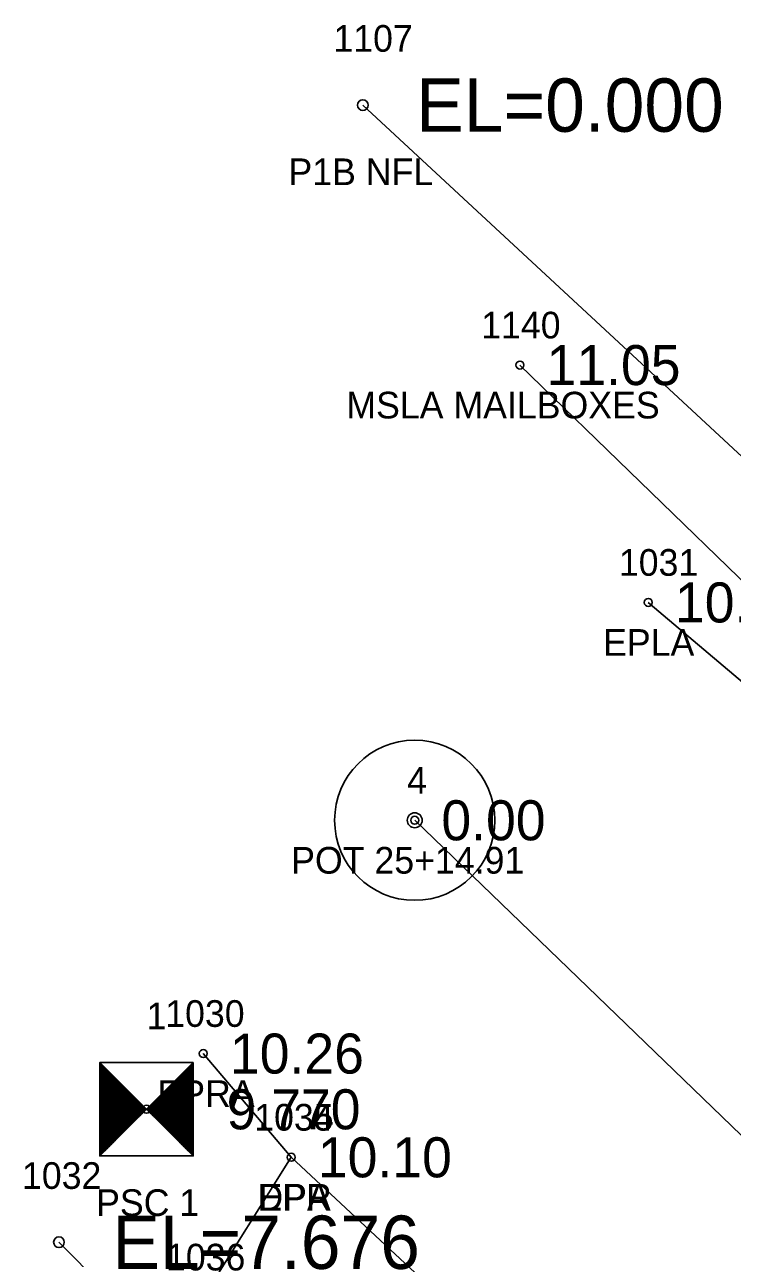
# Model space of a CAD drawing. Extents: x 2608598 to 2610682, y 641451 to 643526.
# Drawn here: x 2608800.2 to 2608826.71, y 643357.31 to 643403.56 of the extents above; entities that cross this region are included whole.
import ezdxf

# ---------------------------------------------------------------- set-up
doc = ezdxf.new("R2010")
doc.units = 0
for name, color, linetype in [('RD_EX_DR_Pipe', 7, 'Continuous'), ('RD_EX_DR_Pipe_txCode', 7, 'Continuous'), ('RD_EX_Driveway', 7, 'Continuous'), ('RD_EX_Driveway_txCode', 7, 'Continuous'), ('RD_EX_Misc', 7, 'Continuous'), ('RD_EX_Misc_txCode', 7, 'Continuous'), ('RD_EX_Road', 7, 'Continuous'), ('RD_EX_Road_txCode', 7, 'Continuous'), ('RD_EX_TX_Driveway_ELEV', 7, 'Continuous'), ('RD_EX_TX_Misc_ELEV', 7, 'Continuous'), ('RD_EX_TX_Road_ELEV', 7, 'Continuous'), ('RD_HC_Cl', 7, 'Continuous'), ('RD_HC_Data', 7, 'Continuous'), ('RD_HC_Survey', 7, 'Continuous'), ('RD_HC_Survey_ELEV', 7, 'Continuous'), ('RD_HC_txCode', 7, 'Continuous'), ('RD_SMD_Locator', 7, 'Continuous'), ('RD_TX_Pipe_ElevEX', 7, 'Continuous')]:
    doc.layers.add(name, color=color, linetype=linetype)

msp = doc.modelspace()

# ---------------------------------------------------------------- linework, layer by layer
at = {"layer": 'RD_EX_DR_Pipe'}
for p, q in [((2608906.801, 643313.376), (2608812.867, 643400.541)), ((2608801.48, 643357.916), (2608816.779, 643342.503))]:
    msp.add_line(p, q, dxfattribs=at)
at = {"layer": 'RD_EX_Driveway'}
msp.add_lwpolyline([(2608810.184, 643361.1), (2608806.9, 643355.858), (2608804.015, 643352.911), (2608810.865, 643346.462), (2608815.199, 643349.433), (2608820.754, 643351.249)], dxfattribs=at)
at = {"layer": 'RD_EX_Misc'}
msp.add_line((2608818.754, 643390.795), (2608829.429, 643380.424), dxfattribs=at)
at = {"layer": 'RD_EX_Road'}
for points in [[(2608823.565, 643381.898), (2608829.584, 643376.805), (2608846.192, 643359.903), (2608852.068, 643354.1), (2608873.124, 643334.611), (2608877.912, 643330.135), (2608897.264, 643311.51), (2608898.769, 643309.298), (2608970.3, 643240.177), (2609042.495, 643170.94), (2609058.512, 643155.458)], [(2608806.889, 643364.989), (2608810.184, 643361.1), (2608820.754, 643351.249), (2608881.81, 643292.235), (2608917.833, 643257.495), (2608933.208, 643242.709), (2608954.068, 643222.833), (2609026.064, 643154.189), (2609039.601, 643139.963), (2609073.879, 643106.954), (2609100.48, 643081.888), (2609124.194, 643058.866), (2609171.612, 643013.711), (2609183.195, 643002.284), (2609197.913, 642988.365), (2609247.586, 642940.954), (2609328.02, 642863.599), (2609402.609, 642790.299), (2609474.235, 642720.69), (2609483.838, 642711.579), (2609495.782, 642699.917), (2609509.808, 642686.45)]]:
    msp.add_lwpolyline(points, dxfattribs=at)
at = {"layer": 'RD_HC_Cl'}
msp.add_line((2608814.812, 643373.733), (2610092.394, 642140.787), dxfattribs=at)
at = {"layer": 'RD_HC_Data'}
for radius in [3, 0.282]:
    msp.add_circle((2608814.812, 643373.733), radius, dxfattribs=at)
at = {"layer": 'RD_HC_Survey'}
for p, q in [((2608803.011, 643364.65), (2608806.511, 643361.15)), ((2608806.511, 643364.65), (2608803.011, 643361.15)), ((2608803.036, 643364.625), (2608803.036, 643361.175)), ((2608803.061, 643364.601), (2608803.061, 643361.2)), ((2608803.086, 643364.576), (2608803.086, 643361.224)), ((2608803.11, 643364.551), (2608803.11, 643361.249)), ((2608803.135, 643364.526), (2608803.135, 643361.274)), ((2608803.16, 643364.502), (2608803.16, 643361.299)), ((2608803.185, 643364.477), (2608803.185, 643361.323)), ((2608803.209, 643364.452), (2608803.209, 643361.348)), ((2608803.234, 643364.427), (2608803.234, 643361.373)), ((2608803.259, 643364.403), (2608803.259, 643361.398)), ((2608803.284, 643364.378), (2608803.284, 643361.422)), ((2608803.308, 643364.353), (2608803.308, 643361.447)), ((2608803.333, 643364.328), (2608803.333, 643361.472)), ((2608803.358, 643364.304), (2608803.358, 643361.497)), ((2608806.165, 643364.304), (2608806.165, 643361.497)), ((2608806.19, 643364.328), (2608806.19, 643361.472)), ((2608806.214, 643364.353), (2608806.214, 643361.447)), ((2608806.239, 643364.378), (2608806.239, 643361.422)), ((2608806.264, 643364.403), (2608806.264, 643361.398)), ((2608806.289, 643364.427), (2608806.289, 643361.373)), ((2608806.313, 643364.452), (2608806.313, 643361.348)), ((2608806.338, 643364.477), (2608806.338, 643361.323)), ((2608806.363, 643364.502), (2608806.363, 643361.299)), ((2608806.388, 643364.526), (2608806.388, 643361.274)), ((2608806.412, 643364.551), (2608806.412, 643361.249)), ((2608806.437, 643364.576), (2608806.437, 643361.224)), ((2608806.462, 643364.601), (2608806.462, 643361.2)), ((2608806.487, 643364.625), (2608806.487, 643361.175)), ((2608803.383, 643364.279), (2608803.383, 643361.521)), ((2608803.407, 643364.254), (2608803.407, 643361.546)), ((2608803.432, 643364.229), (2608803.432, 643361.571)), ((2608803.457, 643364.205), (2608803.457, 643361.596)), ((2608803.482, 643364.18), (2608803.482, 643361.62)), ((2608803.506, 643364.155), (2608803.506, 643361.645)), ((2608803.531, 643364.13), (2608803.531, 643361.67)), ((2608803.556, 643364.106), (2608803.556, 643361.695)), ((2608803.581, 643364.081), (2608803.581, 643361.719)), ((2608803.605, 643364.056), (2608803.605, 643361.744)), ((2608803.63, 643364.031), (2608803.63, 643361.769)), ((2608803.655, 643364.007), (2608803.655, 643361.794)), ((2608803.68, 643363.982), (2608803.68, 643361.818)), ((2608803.704, 643363.957), (2608803.704, 643361.843)), ((2608803.729, 643363.932), (2608803.729, 643361.868)), ((2608803.754, 643363.908), (2608803.754, 643361.893)), ((2608803.779, 643363.883), (2608803.779, 643361.917)), ((2608803.803, 643363.858), (2608803.803, 643361.942)), ((2608805.719, 643363.858), (2608805.719, 643361.942)), ((2608805.744, 643363.883), (2608805.744, 643361.917)), ((2608805.769, 643363.908), (2608805.769, 643361.893)), ((2608805.794, 643363.932), (2608805.794, 643361.868)), ((2608805.818, 643363.957), (2608805.818, 643361.843)), ((2608805.843, 643363.982), (2608805.843, 643361.818)), ((2608805.868, 643364.007), (2608805.868, 643361.794)), ((2608805.893, 643364.031), (2608805.893, 643361.769)), ((2608805.917, 643364.056), (2608805.917, 643361.744)), ((2608805.942, 643364.081), (2608805.942, 643361.719)), ((2608805.967, 643364.106), (2608805.967, 643361.695)), ((2608805.992, 643364.13), (2608805.992, 643361.67)), ((2608806.016, 643364.155), (2608806.016, 643361.645)), ((2608806.041, 643364.18), (2608806.041, 643361.62)), ((2608806.066, 643364.205), (2608806.066, 643361.596)), ((2608806.091, 643364.229), (2608806.091, 643361.571)), ((2608806.115, 643364.254), (2608806.115, 643361.546)), ((2608806.14, 643364.279), (2608806.14, 643361.521)), ((2608803.828, 643363.833), (2608803.828, 643361.967)), ((2608803.853, 643363.809), (2608803.853, 643361.992)), ((2608803.878, 643363.784), (2608803.878, 643362.016)), ((2608803.902, 643363.759), (2608803.902, 643362.041)), ((2608803.927, 643363.734), (2608803.927, 643362.066)), ((2608803.952, 643363.71), (2608803.952, 643362.091)), ((2608803.977, 643363.685), (2608803.977, 643362.115)), ((2608804.001, 643363.66), (2608804.001, 643362.14)), ((2608804.026, 643363.635), (2608804.026, 643362.165)), ((2608804.051, 643363.611), (2608804.051, 643362.19)), ((2608804.076, 643363.586), (2608804.076, 643362.214)), ((2608804.1, 643363.561), (2608804.1, 643362.239)), ((2608804.125, 643363.537), (2608804.125, 643362.264)), ((2608804.15, 643363.512), (2608804.15, 643362.289)), ((2608804.175, 643363.487), (2608804.175, 643362.313)), ((2608804.199, 643363.462), (2608804.199, 643362.338)), ((2608804.224, 643363.438), (2608804.224, 643362.363)), ((2608804.249, 643363.413), (2608804.249, 643362.388)), ((2608804.274, 643363.388), (2608804.274, 643362.412)), ((2608805.249, 643363.388), (2608805.249, 643362.412)), ((2608805.274, 643363.413), (2608805.274, 643362.388)), ((2608805.299, 643363.438), (2608805.299, 643362.363)), ((2608805.323, 643363.462), (2608805.323, 643362.338)), ((2608805.348, 643363.487), (2608805.348, 643362.313)), ((2608805.373, 643363.512), (2608805.373, 643362.289)), ((2608805.398, 643363.537), (2608805.398, 643362.264)), ((2608805.422, 643363.561), (2608805.422, 643362.239)), ((2608805.447, 643363.586), (2608805.447, 643362.214)), ((2608805.472, 643363.611), (2608805.472, 643362.19)), ((2608805.497, 643363.635), (2608805.497, 643362.165)), ((2608805.521, 643363.66), (2608805.521, 643362.14)), ((2608805.546, 643363.685), (2608805.546, 643362.115)), ((2608805.571, 643363.71), (2608805.571, 643362.091)), ((2608805.596, 643363.734), (2608805.596, 643362.066)), ((2608805.62, 643363.759), (2608805.62, 643362.041)), ((2608805.645, 643363.784), (2608805.645, 643362.016)), ((2608805.67, 643363.809), (2608805.67, 643361.992)), ((2608805.695, 643363.833), (2608805.695, 643361.967)), ((2608804.298, 643363.363), (2608804.298, 643362.437)), ((2608804.323, 643363.339), (2608804.323, 643362.462)), ((2608804.348, 643363.314), (2608804.348, 643362.487)), ((2608804.373, 643363.289), (2608804.373, 643362.511)), ((2608804.397, 643363.264), (2608804.397, 643362.536)), ((2608804.422, 643363.24), (2608804.422, 643362.561)), ((2608804.447, 643363.215), (2608804.447, 643362.586)), ((2608804.472, 643363.19), (2608804.472, 643362.61)), ((2608804.496, 643363.165), (2608804.496, 643362.635)), ((2608804.521, 643363.141), (2608804.521, 643362.66)), ((2608804.546, 643363.116), (2608804.546, 643362.685)), ((2608804.571, 643363.091), (2608804.571, 643362.709)), ((2608804.595, 643363.066), (2608804.595, 643362.734)), ((2608804.62, 643363.042), (2608804.62, 643362.759)), ((2608804.645, 643363.017), (2608804.645, 643362.784)), ((2608804.67, 643362.992), (2608804.67, 643362.808)), ((2608804.694, 643362.967), (2608804.694, 643362.833)), ((2608804.719, 643362.943), (2608804.719, 643362.858)), ((2608804.744, 643362.918), (2608804.744, 643362.883)), ((2608804.779, 643362.918), (2608804.779, 643362.883)), ((2608804.804, 643362.943), (2608804.804, 643362.858)), ((2608804.828, 643362.967), (2608804.828, 643362.833)), ((2608804.853, 643362.992), (2608804.853, 643362.808)), ((2608804.878, 643363.017), (2608804.878, 643362.784)), ((2608804.903, 643363.042), (2608804.903, 643362.759)), ((2608804.927, 643363.066), (2608804.927, 643362.734)), ((2608804.952, 643363.091), (2608804.952, 643362.709)), ((2608804.977, 643363.116), (2608804.977, 643362.685)), ((2608805.002, 643363.141), (2608805.002, 643362.66)), ((2608805.026, 643363.165), (2608805.026, 643362.635)), ((2608805.051, 643363.19), (2608805.051, 643362.61)), ((2608805.076, 643363.215), (2608805.076, 643362.586)), ((2608805.101, 643363.24), (2608805.101, 643362.561)), ((2608805.125, 643363.264), (2608805.125, 643362.536)), ((2608805.15, 643363.289), (2608805.15, 643362.511)), ((2608805.175, 643363.314), (2608805.175, 643362.487)), ((2608805.2, 643363.339), (2608805.2, 643362.462)), ((2608805.224, 643363.363), (2608805.224, 643362.437))]:
    msp.add_line(p, q, dxfattribs=at)
msp.add_lwpolyline([(2608806.511, 643364.65), (2608803.011, 643364.65), (2608803.011, 643361.15), (2608806.511, 643361.15)], close=True, dxfattribs=at)
at = {"layer": 'RD_SMD_Locator'}
for centre, radius in [((2608812.867, 643400.541), 0.2), ((2608818.754, 643390.795), 0.15), ((2608823.565, 643381.898), 0.15), ((2608814.812, 643373.733), 0.15), ((2608806.889, 643364.989), 0.15), ((2608804.761, 643362.9), 0.15), ((2608810.184, 643361.1), 0.15), ((2608810.184, 643361.1), 0.15), ((2608801.48, 643357.916), 0.2)]:
    msp.add_circle(centre, radius, dxfattribs=at)

# ---------------------------------------------------------------- texts
at = {"layer": 'RD_EX_DR_Pipe_txCode'}
for s, p in [('1107', (2608811.765, 643402.541)), ('P1B NFL', (2608810.08, 643397.541)), ('1032', (2608800.094, 643359.916))]:
    msp.add_text(s, height=1, dxfattribs=at).set_placement(p)
at = {"layer": 'RD_EX_Driveway_txCode'}
for s, p in [('1035', (2608808.798, 643362.1)), ('DPA', (2608808.916, 643359.1)), ('1036', (2608805.491, 643356.858))]:
    msp.add_text(s, height=1, dxfattribs=at).set_placement(p)
at = {"layer": 'RD_EX_Misc_txCode'}
for s, p in [('1140', (2608817.303, 643391.795)), ('MSLA MAILBOXES', (2608812.25, 643388.795))]:
    msp.add_text(s, height=1, dxfattribs=at).set_placement(p)
at = {"layer": 'RD_EX_Road_txCode'}
for s, p in [('1031', (2608822.463, 643382.898)), ('EPLA', (2608821.872, 643379.898)), ('1030', (2608805.463, 643365.989)), ('EPRA', (2608805.172, 643362.989)), ('1034', (2608808.798, 643362.1)), ('EPR', (2608808.955, 643359.1))]:
    msp.add_text(s, height=1, dxfattribs=at).set_placement(p)
at = {"layer": 'RD_EX_TX_Driveway_ELEV'}
msp.add_text('10.10', height=1.5, dxfattribs=at).set_placement((2608811.184, 643360.35))
at = {"layer": 'RD_EX_TX_Misc_ELEV'}
msp.add_text('11.05', height=1.5, dxfattribs=at).set_placement((2608819.754, 643390.045))
at = {"layer": 'RD_EX_TX_Road_ELEV'}
for s, p in [('10.36', (2608824.565, 643381.148)), ('10.26', (2608807.889, 643364.239)), ('10.10', (2608811.184, 643360.35))]:
    msp.add_text(s, height=1.5, dxfattribs=at).set_placement(p)
at = {"layer": 'RD_HC_Survey_ELEV'}
for s, p in [('0.00', (2608815.812, 643372.983)), ('9.770', (2608807.761, 643362.15))]:
    msp.add_text(s, height=1.5, dxfattribs=at).set_placement(p)
at = {"layer": 'RD_HC_txCode'}
for s, p in [('4', (2608814.528, 643374.733)), ('POT 25+14.91', (2608810.182, 643371.733)), ('1', (2608804.761, 643365.9)), ('PSC 1', (2608802.872, 643358.9))]:
    msp.add_text(s, height=1, dxfattribs=at).set_placement(p)
at = {"layer": 'RD_TX_Pipe_ElevEX'}
for s, p in [('EL=0.000', (2608814.867, 643399.541)), ('EL=7.676', (2608803.48, 643356.916))]:
    msp.add_text(s, height=2, dxfattribs=at).set_placement(p)

doc.saveas('drawing.dxf')
